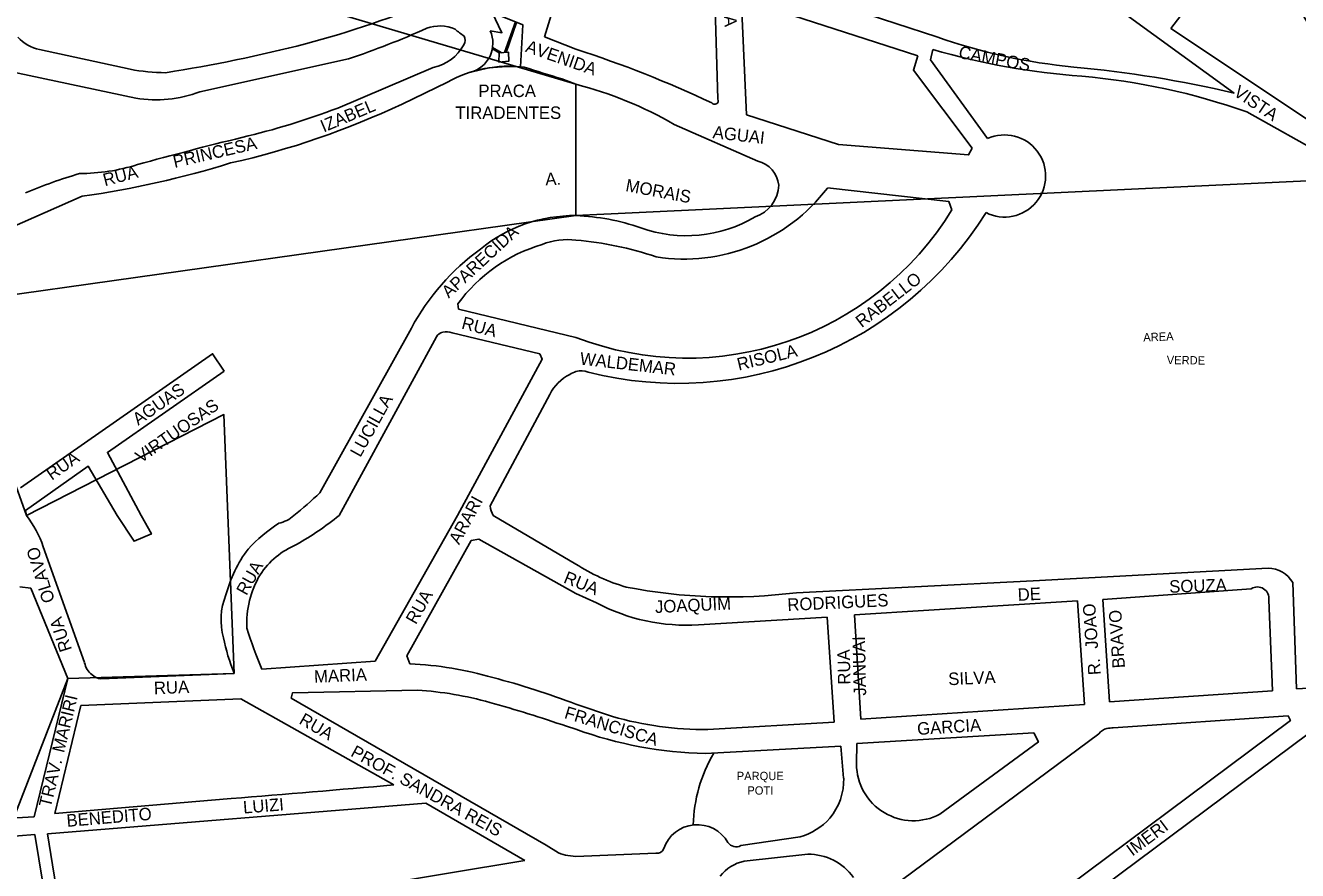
# Model space of a CAD drawing. Extents: x 325709 to 364434, y 7573432 to 7597073.
# Drawn here: x 339017 to 339628, y 7588831 to 7589237 of the extents above; entities that cross this region are included whole.
import ezdxf

# ---------------------------------------------------------------- set-up
doc = ezdxf.new("R2010")
doc.units = 0
for name, color, linetype in [('EDIFIDENTIF', 7, 'Continuous'), ('EDIFOBRAEXIS', 7, 'Continuous'), ('LIMITE_BAIRROS_MUNICIPIOS', 7, 'Continuous'), ('LOGRADOURO', 7, 'Continuous'), ('LOGRADOURO_TEXTO', 7, 'Continuous')]:
    doc.layers.add(name, color=color, linetype=linetype)

msp = doc.modelspace()

# ---------------------------------------------------------------- linework, layer by layer
at = {"layer": 'EDIFOBRAEXIS'}
for p, q in [((339247.08, 7589224.39), (339252.37, 7589239.08)), ((339252.89, 7589238.87), (339247.77, 7589224.44)), ((339241.28, 7589226.79), (339245.83, 7589224.3))]:
    msp.add_line(p, q, dxfattribs=at)
for points in [[(339240.14, 7589234.74), (339245.8, 7589233.86), (339241.07, 7589243.64), (339255.85, 7589237.68), (339254.68, 7589217.44), (339247.93, 7589217.71), (339239.51, 7589216.96), (339230.83, 7589214.94)], [(339241.22, 7589226.17), (339244.43, 7589224.2), (339244.43, 7589224.2)], [(339244.36, 7589219.79), (339244.43, 7589224.2), (339249.05, 7589224.53), (339249.13, 7589220.2), (339244.36, 7589219.79)]]:
    msp.add_lwpolyline(points, dxfattribs=at)
for centre, radius, start, end in [((339227.12, 7589228.77), 14.33, 285.00551, 24.61091), ((339408.81, 7588851.62), 71.1, 149.43287, 178.65839)]:
    msp.add_arc(centre, radius, start, end, dxfattribs=at)
at = {"layer": 'LIMITE_BAIRROS_MUNICIPIOS'}
for points in [[(338912.59, 7589871.56), (339699, 7589756.03), (339790.21, 7589630.89), (339866.96, 7589387.52), (339569.08, 7589346.3), (339676.79, 7589164.86), (339281.39, 7589146.03)], [(339037.18, 7588923.62), (339117.12, 7588926.12), (339112.21, 7589050.43), (339017.39, 7589001.91), (338980.8, 7589103.84), (339281.39, 7589146.03), (339281.39, 7589209.11), (338959.74, 7589304.54)], [(338701.78, 7588902.6), (338907.58, 7588913.12), (339001.31, 7588831.5), (339037.18, 7588923.62)]]:
    msp.add_lwpolyline(points, dxfattribs=at)
at = {"layer": 'LOGRADOURO'}
for p, q in [((339474.83, 7589294.19), (339597.58, 7589204.85)), ((339266.32, 7589231.99), (339279.13, 7589273.52)), ((339567.16, 7589235.93), (339596.16, 7589273.54)), ((339454.81, 7589231.84), (339363.68, 7589261.72)), ((339348.05, 7589253.43), (339349.55, 7589201.91)), ((339445.67, 7589222.84), (339365.65, 7589248.51)), ((339361.09, 7589244.17), (339363.38, 7589194.44)), ((339654.65, 7589177.55), (339567.16, 7589235.93)), ((339281.39, 7589225.95), (339266.32, 7589231.99)), ((339067.13, 7589216.37), (339023.7, 7589225.86)), ((339100.61, 7589205.5), (339172.12, 7589221.3)), ((339212.82, 7589217.2), (339166.9, 7589197.7)), ((339005.82, 7589216.04), (339069.95, 7589202.46)), ((339274.53, 7589211.74), (339281.39, 7589209.11)), ((339197.82, 7589199.63), (339219.7, 7589210.17)), ((339603.7, 7589195.85), (339655.6, 7589166.83)), ((339328.63, 7589189.84), (339368.73, 7589172.21)), ((338997, 7589134.63), (339044.21, 7589155.36)), ((339224.89, 7589101.15), (339224.56, 7589103.58)), ((339281.39, 7589087.49), (339224.89, 7589101.15)), ((339202.34, 7589091.96), (339158.33, 7589012.87)), ((339221.9, 7589089.75), (339263.95, 7589079.61)), ((339167.57, 7589001.91), (339214.41, 7589087.71)), ((339240.13, 7589006.55), (339268.85, 7589060.12)), ((339017.39, 7589001.91), (339016.9, 7589004.43)), ((339224.44, 7589001.91), (339184.89, 7588931.98)), ((339281.39, 7588978.59), (339241.54, 7589001.91)), ((339045.32, 7588931.25), (339025.47, 7588986.95)), ((339234.74, 7588990.51), (339281.39, 7588964.47)), ((339534.55, 7588961.67), (339605.83, 7588966.73)), ((339627.53, 7588918.75), (339625.75, 7588969.71)), ((339281.39, 7588964.47), (339291.26, 7588959.96)), ((339415.17, 7588954.19), (339522.33, 7588960.99)), ((339522.33, 7588960.99), (339525.67, 7588911.08)), ((339537.73, 7588912.42), (339534.55, 7588961.67)), ((339614.24, 7588961.36), (339616.06, 7588917.75)), ((339418.31, 7588904.07), (339415.17, 7588954.19)), ((339340.3, 7588949.46), (339402.12, 7588953.1)), ((339402.12, 7588953.1), (339405.44, 7588902.65)), ((339184.89, 7588931.98), (339130.47, 7588928.05)), ((339037.18, 7588923.62), (339021.07, 7588857.22)), ((339117.12, 7588926.12), (339053.15, 7588923.56)), ((339616.06, 7588917.75), (339537.73, 7588912.42)), ((339687.55, 7588921.8), (339627.53, 7588918.75)), ((339043.49, 7588910.72), (339120.31, 7588913.87)), ((339120.31, 7588913.87), (339193.86, 7588872.5)), ((339298.89, 7588905.35), (339281.39, 7588911.26)), ((339525.67, 7588911.08), (339418.31, 7588904.07)), ((339031.04, 7588858.83), (339043.49, 7588910.72)), ((339646.64, 7588907.17), (339372.26, 7588702.61)), ((339539.56, 7588899.93), (339623.62, 7588905.75)), ((339276.8, 7588900.71), (339281.39, 7588899.24)), ((339405.44, 7588902.65), (339344.73, 7588899.06)), ((339416.27, 7588892.45), (339501.35, 7588897.53)), ((339428.29, 7588819.76), (339532.57, 7588897.09)), ((339343.64, 7588887.56), (339408.58, 7588891.13)), ((339408.58, 7588891.13), (339410, 7588875.77)), ((339416.17, 7588882.57), (339416.27, 7588892.45)), ((339027.55, 7588849.02), (339209.31, 7588863.75)), ((339115.76, 7588865.97), (339031.04, 7588858.83)), ((339209.31, 7588863.75), (339256.83, 7588836.2)), ((339389.13, 7588847.51), (339360.64, 7588843.36)), ((339281.39, 7588838.07), (339277.42, 7588838.63)), ((339319.74, 7588839.69), (339281.39, 7588838.07)), ((339362.22, 7588835.94), (339392.71, 7588839.23)), ((339256.83, 7588836.2), (339111.19, 7588812.13))]:
    msp.add_line(p, q, dxfattribs=at)
for points in [[(339471.67, 7589178.43), (339443.54, 7589215.96), (339445.67, 7589222.84)], [(339479.16, 7589183.01), (339451.69, 7589220.86), (339452.81, 7589225.84)], [(339363.38, 7589194.44), (339407.53, 7589180.2), (339470.02, 7589175.22), (339471.67, 7589178.43)], [(339402.21, 7589159.29), (339460.55, 7589152.75), (339462.01, 7589148.83)], [(339112.41, 7589071.31), (339106.79, 7589079.63), (339014.52, 7589015.21)], [(339263.95, 7589079.61), (339265.22, 7589077.1), (339224.44, 7589001.91)], [(339072.48, 7589001.91), (339056.3, 7589032.23), (339112.41, 7589071.31)], [(339016.9, 7589004.43), (339047.05, 7589025.61), (339060.92, 7589001.91)], [(339060.92, 7589001.91), (339069.1, 7588989.55), (339077.39, 7588993.13), (339072.48, 7589001.91)], [(339201.55, 7588930.66), (339200.18, 7588934.48), (339231.07, 7588989.9), (339234.74, 7588990.51)], [(339613.89, 7588976.57), (339501.11, 7588970.56), (339387.39, 7588964.86)], [(339014.17, 7588967.62), (339019.4, 7588967.05), (339037.18, 7588923.62)], [(339021.07, 7588857.22), (338998.25, 7588855.97), (338962.2, 7588876.38), (338933.33, 7588925.66)], [(339144.55, 7588914.14), (339145.24, 7588916.8), (339205.23, 7588918.08)], [(338920.06, 7588914.62), (338928.19, 7588915.13), (338955.8, 7588868.66), (338997.67, 7588846.78), (339021.33, 7588848.72)], [(339273.03, 7588839.92), (339267.09, 7588843.53), (339144.55, 7588914.14)], [(339623.62, 7588905.75), (339624.66, 7588903.44), (339458.92, 7588779.79)], [(339501.35, 7588897.53), (339503.58, 7588893.19), (339456.28, 7588858.47)], [(339021.33, 7588848.72), (339027.31, 7588812.67), (339036.92, 7588786.09)], [(339043.28, 7588788.52), (339033.32, 7588813.27), (339027.55, 7588849.02)]]:
    msp.add_lwpolyline(points, dxfattribs=at)
for centre, radius, start, end in [((339033.13, 7589675.67), 462.53, 284.8251, 293.05325), ((339038.49, 7589617.94), 418.54, 288.6199, 294.13952), ((339215.96, 7589219.16), 17.98, 65.80764, 110.53111), ((339254.9, 7589272.43), 48.54, 229.43031, 235.77457), ((339027.55, 7589245.02), 19.54, 222.96737, 258.63279), ((339224.04, 7589230.33), 4.06, 326.96644, 28.91032), ((339546.76, 7589493.87), 277.7, 250.66336, 264.60624), ((338973.01, 7589924.84), 718.81, 278.89943, 284.37628), ((339208.51, 7589238.23), 21.46, 281.58694, 331.89617), ((339114.4, 7588708.05), 544.16, 64.73825, 72.12831), ((339547.89, 7589549.89), 337.71, 253.64642, 266.01455), ((339249.09, 7589157.23), 60.55, 83.01038, 119.03859), ((339736.47, 7590738.62), 1595.22, 252.48788, 253.16742), ((339470.69, 7588668.92), 550.75, 76.67916, 84.79452), ((339084.06, 7589300.71), 86.02, 258.65292, 270.09849), ((339496.13, 7588890.44), 323.8, 70.59743, 84.98734), ((339079.64, 7589260.83), 59.17, 260.56815, 290.75485), ((339234.35, 7589026.31), 188.76, 60.03391, 75.56809), ((339030.24, 7589553.52), 391.57, 282.56834, 295.33977), ((339348.07, 7589201.47), 1.95, 221.92956, 291.80818), ((339348.06, 7589201.16), 1.67, 295.98602, 26.67978), ((339043.01, 7589519.52), 344.84, 283.05075, 291.05469), ((339574.25, 7587340.35), 1898.17, 103.81823, 105.38434), ((339487.32, 7589165.05), 19.73, 243.11168, 114.44663), ((339042.46, 7589261), 94.79, 270.24132, 287.31609), ((338983.15, 7589594.25), 443.12, 277.9204, 287.37017), ((339365.71, 7589159.4), 13.15, 5.29698, 76.74793), ((339115.38, 7588921.62), 255.11, 106.5159, 112.71344), ((339333.32, 7589211.72), 86.57, 261.1252, 322.72087), ((339362.04, 7589161.29), 16.78, 288.78263, 357.70426), ((339280.76, 7589074.21), 71.83, 89.49572, 129.1017), ((339334.85, 7589226.67), 149.1, 248.98786, 328.52548), ((339277.15, 7589037.92), 108.2, 70.92688, 87.75567), ((339330.46, 7589239.87), 174.44, 255.65051, 328.00711), ((339334.45, 7589200.96), 64.62, 250.15678, 300.70515), ((339287.42, 7589057.51), 77.93, 106.60119, 143.76713), ((339277.46, 7589100.33), 34.16, 83.39208, 111.11994), ((339267.51, 7588971.84), 163.02, 71.22917, 85.11385), ((339301.14, 7589039.26), 111.98, 125.91505, 151.9244), ((339218.14, 7589085.95), 4.13, 101.19515, 154.77463), ((339219.08, 7589079.86), 10.29, 74.10244, 99.71987), ((339285.33, 7589058.35), 13.37, 107.14179, 121.38059), ((339283.89, 7589061.2), 10.23, 70.97047, 104.13475), ((339288.37, 7589050.36), 21.83, 117.27903, 153.45623), ((339024.94, 7589152.03), 192.76, 308.85417, 313.79016), ((339263.44, 7589011.1), 23.75, 191.0394, 202.74596), ((338975.22, 7588969.47), 53.2, 19.18559, 37.57589), ((339187.81, 7588925.04), 88.22, 123.91429, 136.46267), ((339135.49, 7589013.5), 15.55, 281.48854, 311.84486), ((339067.17, 7589127.22), 160.57, 299.88821, 308.70292), ((339175.27, 7588947.36), 64.21, 143.20636, 165.19724), ((339162.27, 7588951.91), 39.12, 112.68217, 146.64617), ((339331.38, 7589056.02), 92.16, 237.15558, 253.67622), ((339170.73, 7588949.61), 47.54, 149.94476, 182.24074), ((339614.16, 7588963.35), 13.22, 28.7335, 91.18676), ((339354.88, 7589220.61), 257.81, 258.95196, 277.24469), ((339608.84, 7588962.18), 5.46, 351.46016, 123.4355), ((339141.83, 7588951.87), 31, 157.43338, 196.19369), ((339334.3, 7589041.23), 91.97, 242.0959, 273.74336), ((339407.15, 7589040.79), 298.77, 198.14392, 202.16933), ((339206.66, 7588961.95), 96.44, 191.19832, 201.80547), ((339054.1, 7588932.67), 8.9, 189.2268, 233.78461), ((339194.84, 7588765.48), 165.31, 73.64759, 87.67534), ((339053.28, 7588929.59), 6.04, 222.73426, 268.69381), ((339152.28, 7588577.76), 357.62, 68.83654, 75.57206), ((339193.99, 7588747.23), 171.21, 74.4141, 86.23547), ((339074.48, 7588314.84), 619.81, 70.94855, 74.51171), ((339344.46, 7589067.54), 168.47, 254.30416, 270.09226), ((339348.25, 7589083.89), 196.38, 250.09548, 268.65492), ((339538.17, 7588892.85), 7.02, 104.32912, 142.84892), ((339540.25, 7588874.5), 25.44, 91.5634, 98.62948), ((339443.52, 7588882.66), 27.35, 180.18153, 297.8097), ((339381.4, 7588874.89), 28.62, 320.03331, 1.76549), ((338008.06, 7602582.97), 13761.65, 274.616865, 274.943162), ((339380.47, 7588876.89), 30.62, 286.41964, 318.27876), ((339339.65, 7588836.34), 17.06, 30.1767, 160.70272), ((339358.36, 7588847.54), 4.76, 213.55955, 298.55933), ((339279.07, 7588852.4), 13.87, 244.15399, 263.16687), ((339320.37, 7588842.95), 3.32, 259.03744, 342.86213), ((339393.01, 7588812.51), 26.72, 35.6031, 90.64455), ((339367.17, 7588815.09), 21.42, 103.34203, 140.61597)]:
    msp.add_arc(centre, radius, start, end, dxfattribs=at)

# ---------------------------------------------------------------- texts
at = {"layer": 'EDIFIDENTIF'}
for s, rotation, p in [('AREA', 2.24578, (339554.03, 7589085.53)), ('VERDE', 359.13678, (339565.21, 7589074.71))]:
    msp.add_text(s, height=4, rotation=rotation, dxfattribs=at).set_placement(p)
for s, p in [('PARQUE', (339358.64, 7588874.82)), ('POTI', (339363.73, 7588867.85))]:
    msp.add_text(s, height=4, dxfattribs=at).set_placement(p)
at = {"layer": 'LOGRADOURO_TEXTO'}
for s, rotation, p in [('RITA', 274.55732, (339351.43, 7589254.76)), ('AVENIDA', 340.74931, (339256.71, 7589224.86)), ('CAMPOS', 349.31068, (339464.91, 7589221.76)), ('VISTA', 326.28698, (339596.89, 7589204.03)), ('IZABEL', 23.01211, (339160.19, 7589185.88)), ('AGUAI', 353.36044, (339346.88, 7589183.27)), ('PRINCESA', 13.06334, (339088.56, 7589168.89)), ('RUA', 14.49765, (339055.03, 7589160.13)), ('A.', 2.37337, (339266.78, 7589160.55)), ('MORAIS', 349.26526, (339304.9, 7589157.83)), ('APARECIDA', 42.75491, (339220.27, 7589106.05)), ('RABELLO', 37.69912, (339418.67, 7589091.92)), ('RUA', 345.18645, (339226.04, 7589091.84)), ('RISOLA', 13.67773, (339359.6, 7589071.53)), ('WALDEMAR', 353.43837, (339283.03, 7589074.49)), ('AGUAS', 34.92123, (339071.04, 7589045.03)), ('LUCILLA', 60.90685, (339177.77, 7589029.56)), ('VIRTUOSAS', 34.92123, (339072.38, 7589026.96)), ('RUA', 34.92123, (339029.54, 7589018.62)), ('ARARI', 61.52745, (339225.23, 7588987.61)), ('OLAVO', 107.12375, (339031.09, 7588961.01)), ('RUA', 60.90685, (339123.09, 7588963.16)), ('RUA', 338.24042, (339275.02, 7588969.83)), ('DE', 2.70674, (339493.76, 7588960.91)), ('SOUZA', 1.73471, (339566.51, 7588964.8)), ('RUA', 60.50411, (339204.48, 7588949.25)), ('JOAQUIM', 2.70674, (339319.5, 7588955.06)), ('RODRIGUES', 2.70674, (339383.1, 7588956.08)), ('JOAO', 93.70208, (339532.27, 7588938.05)), ('BRAVO', 93.70208, (339545.17, 7588928.75)), ('RUA', 107.86122, (339039.29, 7588937.58)), ('JANUAI', 91.26187, (339420.85, 7588915.47)), ('RUA', 91.26187, (339413.31, 7588920.76)), ('R.', 93.70208, (339533.56, 7588925.48)), ('MARIA', 2.29987, (339155.65, 7588921.58)), ('SILVA', 2.64277, (339460.39, 7588920.38)), ('RUA', 2.29987, (339078.71, 7588916.06)), ('MARIRI', 76.36386, (339035.42, 7588887.65)), ('RUA', 330.05005, (339147.9, 7588902.2)), ('FRANCISCA', 343.0306, (339275.41, 7588904.69)), ('GARCIA', 3.58352, (339445.49, 7588896.49)), ('PROF. SANDRA REIS', 331.11909, (339172.7, 7588886.63)), ('TRAV.', 76.36386, (339029.05, 7588861.38)), ('LUIZI', 4.6369, (339121.69, 7588858.73)), ('BENEDITO', 4.8164, (339036.88, 7588852.33)), ('IMERI', 36.72508, (339548.69, 7588838.06))]:
    msp.add_text(s, height=6, rotation=rotation, dxfattribs=at).set_placement(p)
for s, p in [('PRACA', (339234.51, 7589202.96)), ('TIRADENTES', (339223.46, 7589192.45))]:
    msp.add_text(s, height=6, dxfattribs=at).set_placement(p)

doc.saveas('drawing.dxf')
